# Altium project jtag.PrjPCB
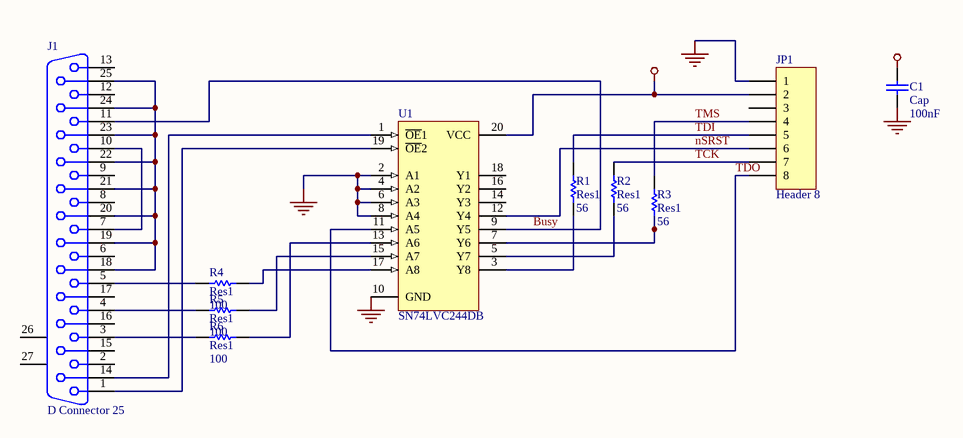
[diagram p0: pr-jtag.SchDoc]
1 sheet, 10 parts. Net scope: global (net labels, ports and power ports of the same name join across sheets).
Board file: pr-jtag.PcbDoc

## Sheet pr-jtag.SchDoc
size B

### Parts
C1  Cap  value 100nF  [res 5mm]
J1  D Connector 25  [DB25-tapa]
JP1  Header 8  [HDR2X4]
R1  Res1  value 56  [Res 5mm]
R2  Res1  value 56  [Res 5mm]
R3  Res1  value 56  [Res 5mm]
R4  Res1  value 100  [Res 5mm]
R5  Res1  value 100  [Res 5mm]
R6  Res1  value 100  [Res 5mm]
U1  SN74LVC244DB  [SO-G20]

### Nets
GND: C1.1 JP1.1 U1.2(A1) U1.4(A2) U1.6(A3) U1.8(A4) U1.10(GND)
VCC: C1.2 JP1.2 U1.20(VCC)
Busy: J1.11 U1.9(Y5)
nSRST: JP1.6 U1.12(Y4)
TCK: JP1.7 R2.2
TDI: JP1.5 R1.2
TDO: JP1.8 U1.11(A5)
TMS: JP1.4 R3.2
NetJ1_1: J1.1 U1.19(~{OE}2)
NetJ1_3: J1.3 R6.1
NetJ1_4: J1.4 R5.1
NetJ1_5: J1.5 R4.1
NetJ1_7: J1.7 J1.10
NetJ1_14: J1.14 U1.1(~{OE}1)
NetJ1_18: J1.18 J1.19 J1.20 J1.21 J1.22 J1.23 J1.24 J1.25
NetR1_1: R1.1 U1.3(Y8)
NetR2_1: R2.1 U1.5(Y7)
NetR3_1: R3.1 U1.7(Y6)
NetR4_2: R4.2 U1.17(A8)
NetR5_2: R5.2 U1.15(A7)
NetR6_2: R6.2 U1.13(A6)

Not connected (* = marked no-connect by the designer): J1 2 6 8 9 12 13 15 16 17 26(MH1) 27(MH2); JP1 3; U1 14(Y3) 16(Y2) 18(Y1)

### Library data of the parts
C1 = Cap: Capacitor; Manufacturer: Generic Components; Class I: Passive
J1 = D Connector 25: Receptacle Assembly, 25 Position, Right Angle; Manufacturer: Generic Components; Package Information: Latest Revision: U; Positions: 25
JP1 = Header 8: Header, 8-Pin; Manufacturer: Generic Components; Class I: Connector
R1-R6 = Res1: Resistor; Manufacturer: Generic Components; Class I: Passive
U1 = SN74LVC244DB: Octal Buffer/Driver with 3-State Outputs; Manufacturer: Texas Instruments; Package Information: Latest Revision: May-1999; Class I: Logic; Class II: Buffer/Line Driver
